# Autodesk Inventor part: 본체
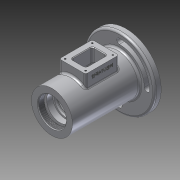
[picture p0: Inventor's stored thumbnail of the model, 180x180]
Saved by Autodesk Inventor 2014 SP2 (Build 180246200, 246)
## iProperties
Created: 2017-05
Part Number: 본체
Material: 알루미늄 6061
Document SubType Name: Modeling
Designer: 거성
Density: 2.71 g/cm^3
Appearance: 알루미늄 - 평지
Mass: 678.667 g
Surface Area: 616.172 cm^2
Volume: 250.431 cm^3
Author: 거성
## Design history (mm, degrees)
sketch "스케치1"
  geometry: C1 r 31 at (0, 0); 1 further point
  constraints: 1 centre point, 1 coincident
  dimensions: "d0" = 62 diameter of C1
extrude "돌출1" new body sketch "스케치1" stored distance "d1" = 115; taper "d2" = 0 deg
node "작업 평면1"
sketch "스케치2"
  geometry: L1 (31, 57.5)-(-31, 57.5) reference; L2 (0, 57.5)-(0, -57.5); L3 (-31, -57.5)-(31, -57.5) reference; L4 (21, 57.5)-(21, 48.5); L5 (21, 48.5)-(24, 48.5); L6 (24, 48.5)-(24, 45.5); L7 (24, 45.5)-(20, 45.5); L8 (20, 45.5)-(20, 36.5); L9 (20, 36.5)-(17.5, 36.5); L10 (17.5, 36.5)-(17.5, 33.25); L11 (17.5, 33.25)-(18.5, 33.25); L12 (18.5, 33.25)-(18.5, 31.5); L13 (18.5, 31.5)-(17.5, 31.5); L14 (17.5, 31.5)-(17.5, 20.5); L15 (17.5, 20.5)-(23, 20.5); L16 (23, -17.5)-(17.5, -17.5); L17 (17.5, -17.5)-(17.5, -28.5); L18 (17.5, -28.5)-(16.5, -28.5); L19 (16.5, -28.5)-(16.5, -30.5); L20 (13.5, -33.5)-(10, -33.5); L21 (10, -33.5)-(10, -36.2); L22 (16.5, -43.5)-(22, -57.5); L23 (0, -57.5)-(22, -57.5); L24 (21, 57.5)-(0, 57.5); L25 (10, -36.2)-(12.2, -36.2); L26 (12.5, -36.5)-(12.5, -42.8); L27 (12.904, -43.5)-(16.5, -43.5); L28 (12.5, -42.8)-(12.904, -43.5); L29 (12.5, -42.8)-(16.75, -42.8); L30 (26, 17.5)-(26, -14.5); A1 r 0.3 centre (12.2, -36.5) between (12.5, -36.5) and (12.2, -36.2); A2 r 3 centre (13.5, -30.5) between (13.5, -33.5) and (16.5, -30.5); A3 r 3 centre (23, 17.5) between (26, 17.5) and (23, 20.5); A4 r 3 centre (23, -14.5) between (23, -17.5) and (26, -14.5); 7 further points
  constraints: 56 end point, 14 parallel, 10 point on line, 8 perpendicular, 8 point on circle, 8 tangent, 4 centre point, 3 collinear, 3 midpoint, 2 horizontal, 1 equal radius, 1 vertical, 4 other
  dimensions: "d22" = 60 deg angle of L28 L29; "d23" = 0.7 vertical distance of L26.end L27.start; "d32" = 12 vertical distance of L6.end L4.start; "d33" = 3 distance of L5.end L6.end; "d34" = 21 vertical distance of L4.start L8.end; "d35" = 26 vertical distance of L4.start L12.end; "d42" = 42 diameter of L4 L2; "d43" = 48 diameter of L6 L2; "d44" = 40 diameter of L8 L2; "d45" = 1.75 distance of L11.end L12.end; "d46" = 37 diameter of L12 L2; "d50" = 3 radius of A3; "d51" = 11 distance of L13.end L14.end; "d52" = 11 distance of L16.end L17.end; "d53" = 38 distance between parallel lines of L16 L15; "d55" = 52 diameter of L30 L2; "d56" = 5 vertical distance of L20.start L18.end; "d57" = 2.7 distance of L20.end L21.end; "d58" = 7.3 vertical distance of L27.start L25.end; "d59" = 14 vertical distance of L22.start L22.end; "d60" = 33 diameter of L22.start L2; "d61" = 44 diameter of L22.end L2; "d62" = 20 diameter of L21 L2; "d63" = 25 diameter of L26 L2; "d64" = 33 diameter of L19 L2; "d65" = 35 diameter of L17 L2; "d66" = 3 radius of A2; "d67" = 0.3 radius of A1; "d68" = 4.25045 distance of L26.end L29.end
revolve "회전1" sketch "스케치2" stored, may be unused: angle "d69" = 90 deg
node "작업 평면2"
node "작업 평면3"
node "작업 평면4"
sketch "스케치5"
  geometry: C1 r 31 at (0, 0) reference; C2 r 53 at (0, 0); 1 further point
  constraints: 1 centre point, 1 coincident
  dimensions: "d81" = 106 diameter of C2
extrude "돌출4" join sketch "스케치5" distance "d82" = 10; taper "d83" = 0 deg
feature "스레드1" dims "d90" = 10, "d91" = 0
fillet "모깎기3" dims "d95" = 3
node "작업 평면5"
sketch "스케치7"
  geometry: L1 (20, -23.5)-(-20, -23.5); L2 (-20, -23.5)-(-20, 26.5); L3 (-20, 26.5)-(20, 26.5); L4 (20, 26.5)-(20, -23.5); L5 (31, 57.5)-(-31, 57.5) reference; L6 (20, 1.5)-(-20, 1.5); 2 further points
  constraints: 10 end point, 3 midpoint, 2 parallel, 1 horizontal, 1 perpendicular, 1 vertical alignment
  dimensions: "d97" = 40 distance of L2.end L3.end; "d98" = 50 distance of L1.end L2.end; "d100" = 56 distance between parallel lines of L6 L5
extrude "돌출6" join sketch "스케치7" stored distance "d101" = 10; taper "d102" = 0 deg
sketch "스케치8"
  geometry: L1 (-15.5, 19)-(15.5, 19); L2 (15.5, 19)-(15.5, -22); L3 (15.5, -22)-(-15.5, -22); L4 (-15.5, -22)-(-15.5, 19); L5 (15.5, -1.5)-(-15.5, -1.5); L6 (-31, -57.5)-(31, -57.5) reference; L7 (-11, 14.5)-(11, 14.5); L8 (11, 14.5)-(11, -17.5); L9 (11, -17.5)-(-11, -17.5); L10 (-11, -17.5)-(-11, 14.5); L11 (11, -1.5)-(-11, -1.5); 4 further points
  constraints: 20 end point, 7 midpoint, 4 parallel, 2 horizontal, 2 perpendicular, 2 vertical alignment
  dimensions: "d103" = 31 distance of L2.end L3.end; "d104" = 41 distance of L3.end L1.start; "d105" = 56 distance between parallel lines of L6 L5; "d106" = 32 distance of L7.end L8.end; "d107" = 22 distance of L8.end L9.end; "d108" = 56 distance between parallel lines of L6 L11
extrude "돌출7" cut sketch "스케치8" stored distance "d109" = 30; taper "d110" = 0 deg
hole "구멍1" sketch "스케치8" diameter "d111" = 2.459; stored, may be unused: countersink angle "d115" = 90 deg, drill point angle "d117" = 118 deg; dims "d112" = 6, "d113" = 4, "d114" = 2, "d116" = 8
fillet "모깎기4" dims "d118" = 3
fillet "모깎기5" dims "d119" = 3
chamfer "모따기2" distance "d120" = 1; stored, may be unused: second distance "d121" = 2, angle "d122" = 45 deg
sketch "스케치9"
  geometry: C1 r 31 at (0, 0) reference; C2 r 53 at (0, 0) reference; A1 r 41.5 centre (0, 0) between (41.5, 0) and (0, 41.5); A2 r 4 centre (41.5, 0) between (37.5, 0) and (45.5, 0); A3 r 4 centre (0, 41.5) between (0, 37.5) and (0, 45.5); A4 r 4 centre (-41.5, 0) between (-37.5, 0) and (-45.5, 0); A5 r 4 centre (0, -41.5) between (0, -37.5) and (0, -45.5); A6 r 37.5 centre (0, 0) between (0, 37.5) and (-37.5, 0); A7 r 37.5 centre (0, 0) between (0, -37.5) and (37.5, 0); A8 r 45.5 centre (0, 0) between (0, 45.5) and (-45.5, 0); A9 r 45.5 centre (0, 0) between (0, -45.5) and (45.5, 0)
  constraints: 20 point on circle, 9 centre point, 2 horizontal alignment, 2 vertical alignment, 1 coincident
  dimensions: "d123" = 83 diameter of A1; "d124" = 8 diameter of A2; "d125" = 8 diameter of A3; "d126" = 8 diameter of A4; "d127" = 8 diameter of A5; "d128" = 37.5 radius of A7; "d129" = 45.5 radius of A9; "d130" = 37.5 radius of A6; "d131" = 45.5 radius of A8
extrude "돌출8" cut sketch "스케치9" distance "d132" = 10; taper "d133" = 0 deg
chamfer "모따기3" distance "d134" = 1; stored, may be unused: second distance "d135" = 2, angle "d136" = 45 deg
sketch "스케치10"
  geometry: L1 (44, 0)-(0, 0) reference; L2 (-34, -13)-(-34, -75) reference; 2 further points
  constraints: 1 other
  dimensions: "d137" = 56 distance from line of point (22, -8) L2; "d138" = 8 distance from line of point (22, -8) L1
feature "엠보싱1" sketch "스케치10" dims "d139" = 0.5, "d140" = 0
fillet "모깎기6" dims "d141" = 3
fillet "모깎기7" dims "d142" = 0.3
chamfer "모따기4" distance "d143" = 1; stored, may be unused: second distance "d144" = 2, angle "d145" = 45 deg
node "솔리드1"
other parameters: "d3" = 0, "d70" = -3, "d74" = 44, "d80" = -3, "d96" = 44
